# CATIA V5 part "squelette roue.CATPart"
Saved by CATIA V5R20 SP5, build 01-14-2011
Part number: squelette roue
Bounding box of the stored display mesh (mm): x 0 to 0, y -10000 to 10000, z 0 to 0
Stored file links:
  M:\EU_thinkMotion\IAO_2010\iao\IAO_MMS_Groupe1\Problemes\gduval\Gduval\train d'aterrissage squelette + piece kinematic\squelette roue.CATPart
  M:\EU_thinkMotion\IAO_2010\iao\IAO_MMS_Groupe1\Problemes\gduval\Gduval\train d'aterrissage squelette + piece kinematic\train d'aterrissage.CATProduct
  M:\EU_thinkMotion\IAO_2010\iao\IAO_MMS_Groupe1\Problemes\gduval\Gduval\train d'aterrissage squelette + piece kinematic\squelette de base.CATPart
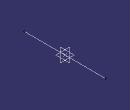
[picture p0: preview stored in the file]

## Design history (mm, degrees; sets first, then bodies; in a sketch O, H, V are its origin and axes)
Set1
  Plane1: linked copy from another document
  Point1: linked copy from another document
Body1 (main body)
  Line1: type Normal, RefPoint Point1, RefSkin Plane1, Start -10000, End 10000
